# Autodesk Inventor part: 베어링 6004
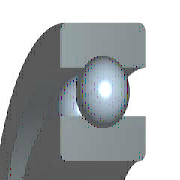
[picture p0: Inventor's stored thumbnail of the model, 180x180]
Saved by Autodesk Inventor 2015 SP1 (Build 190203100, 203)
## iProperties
Created: 2012-02
Part Number: 베어링 6004
Material: 강철, 연강
Description: 깊은 그루브 볼 베어링
Document SubType Name: Modeling
Standard: KS B 2023
Designer: mduedu
Standards Organization: KS
Language: ko-KR
Size Designation: 6004 - 20 x 42 x 12
Categories: <MemberInstance><Categories><Category DisplayName="샤프트 부품" InternalName="7f7aeb1f-a693-4053-b835-cee3144e0d98" Mnemonic="SHFT"><Category DisplayName="베어링" Inter
Density: 1 g/cm^3
Appearance: 노란색
IsCustomPart: 1
Author: mduedu
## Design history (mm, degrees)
sketch "스케치" dims "d0" = 5.72 (= -0.26 x WD + 0.26 x BD)
  geometry: L1 (3.14, 15.5)-(8.86, 15.5); L2 (6, 15.5)-(6, 12.64); L3 (6, 15.5)-(6, 18.36); L4 (3.875, 13.586)-(0, 13.586); L5 (0, 10)-(12, 10); L6 (3.875, 17.414)-(0, 17.414); L7 (0, 21)-(12, 21); L8 (12, 10)-(12, 13.586); L9 (8.125, 13.586)-(12, 13.586); L10 (8.125, 17.414)-(12, 17.414); L11 (12, 21)-(12, 17.414); L12 (-1.4, 0)-(8.4, 0) reference; L13 (0, -0.3)-(0, 5.3) reference
  constraints: 22 end point, 4 point on line, 2 collinear, 2 perpendicular, 2 symmetric about line, 1 midpoint, 1 parallel, 14 other
  dimensions: "d9" = 20 diameter of L5 L12 (= WD); "d11" = 42 diameter of L7 L12 (= BD); "d12" = 12 distance between parallel lines of L8 L13 (= KB); "d13" = 27.172 diameter of L9 L12 (= 0.326 x BD + 0.674 x WD)
revolve "본체" stored, may be unused: angle "d6" = 90 deg
revolve "볼" stored, may be unused: angle "d7" = 90 deg
pattern_circular "IDS_ARRAYBALL[SIMPL:T]" dims angle "d3" = 360 deg
body "Solid1"
fillet "모깎기1" dims "d1" = 0.6 (= KRS)
other parameters: "WD" = 20 [user parameter; used in 5 equation terms], "BD" = 42 [user parameter; used in 5 equation terms], "KB" = 12 [user parameter; used in 1 equation term], "KRS" = 0.6 [user parameter; used in 1 equation term], "d4" = 0, "d5" = 0, "d8" = 0, "d14" = 0, "d15" = 0, "BBA" = 0 [user parameter], "BC0" = 5000000 [user parameter], "BC" = 9360000 [user parameter], "BR" = 21 (= 0.5 x BD) [user parameter]
